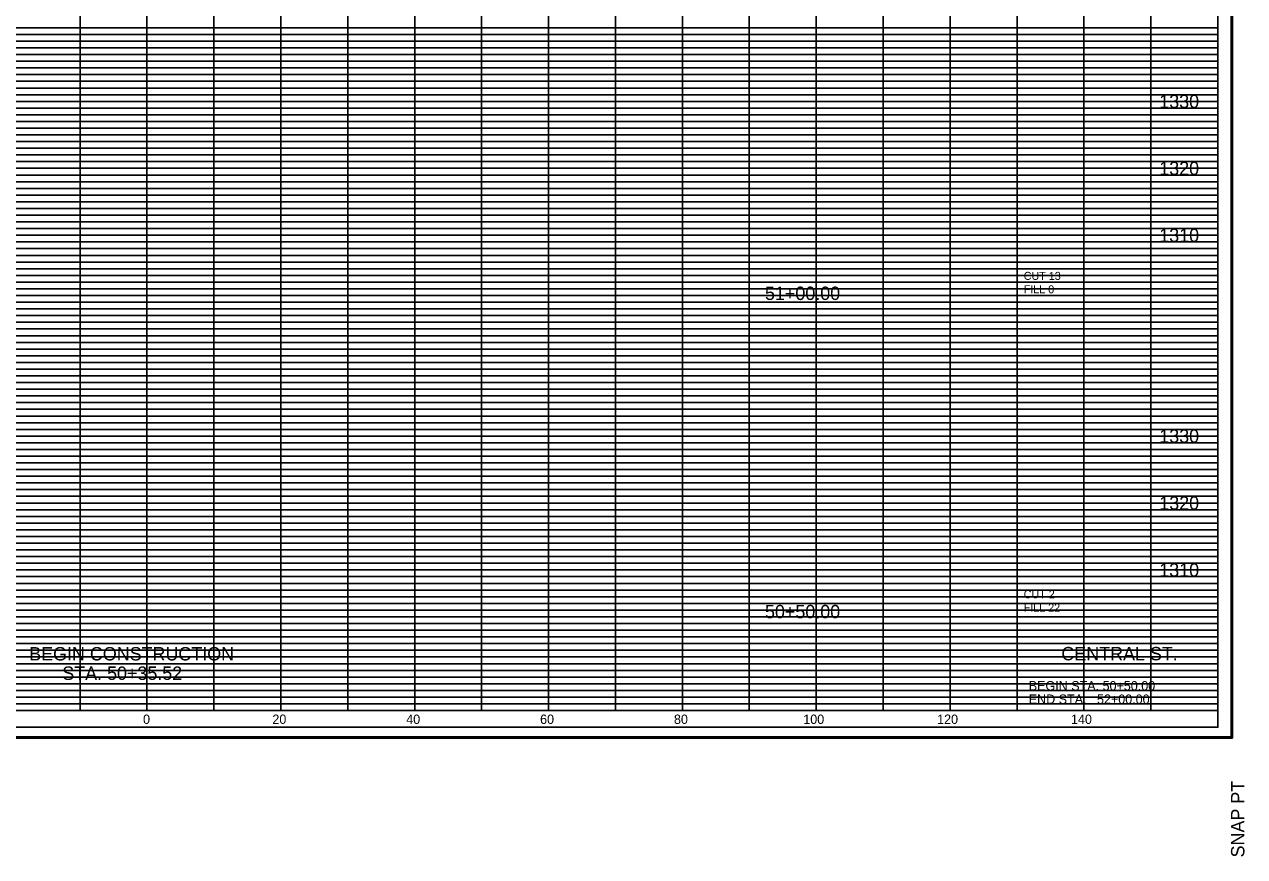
# Model space of a CAD drawing. Extents: x 980 to 1324, y 978 to 1227.
# Drawn here: x 1141.7 to 1324, y 978.2 to 1102.5 of the extents above; entities that cross this region are included whole.
import ezdxf

# ---------------------------------------------------------------- set-up
doc = ezdxf.new("R2010")
doc.units = 0
for name, color, linetype in [('DESIGN - SHEET - Corner Text', 7, 'Continuous'), ('DESIGN - SHEET - Light Grid', 7, 'Continuous'), ('DESIGN - SHEET - Linework', 7, 'Continuous'), ('DESIGN - SHEET - Plot Shape', 7, 'Continuous'), ('DESIGN - TYPICAL - Finished Grade and Subgrade', 7, 'Continuous'), ('DESIGN - TYPICAL - Text', 7, 'Continuous')]:
    doc.layers.add(name, color=color, linetype=linetype)

# ---------------------------------------------------------------- blocks, each defined once
blk = doc.blocks.new('XSTSHT')
at = {"layer": 'DESIGN - SHEET - Light Grid'}
for p, q in [((8, 10.2), (16, 10.2)), ((8, 10.1), (16, 10.1)), ((16, 10.2), (24, 10.2)), ((16, 10.1), (24, 10.1)), ((24, 10.2), (32, 10.2)), ((24, 10.1), (32, 10.1)), ((8, 9.9), (16, 9.9)), ((16, 9.9), (24, 9.9)), ((24, 9.9), (32, 9.9)), ((8, 9.8), (16, 9.8)), ((8, 9.7), (16, 9.7)), ((16, 9.8), (24, 9.8)), ((16, 9.7), (24, 9.7)), ((24, 9.8), (32, 9.8)), ((24, 9.7), (32, 9.7)), ((8, 9.6), (16, 9.6)), ((8, 9.5), (16, 9.5)), ((16, 9.6), (24, 9.6)), ((16, 9.5), (24, 9.5)), ((24, 9.6), (32, 9.6)), ((24, 9.5), (32, 9.5)), ((8, 9.4), (16, 9.4)), ((8, 9.3), (16, 9.3)), ((16, 9.4), (24, 9.4)), ((16, 9.3), (24, 9.3)), ((24, 9.4), (32, 9.4)), ((24, 9.3), (32, 9.3)), ((8, 9.2), (16, 9.2)), ((16, 9.2), (24, 9.2)), ((24, 9.2), (32, 9.2)), ((8, 9.1), (16, 9.1)), ((16, 9.1), (24, 9.1)), ((24, 9.1), (32, 9.1)), ((8, 8.9), (16, 8.9)), ((8, 8.8), (16, 8.8)), ((16, 8.9), (24, 8.9)), ((16, 8.8), (24, 8.8)), ((24, 8.9), (32, 8.9)), ((24, 8.8), (32, 8.8)), ((8, 8.7), (16, 8.7)), ((8, 8.6), (16, 8.6)), ((16, 8.7), (24, 8.7)), ((16, 8.6), (24, 8.6)), ((24, 8.7), (32, 8.7)), ((24, 8.6), (32, 8.6)), ((8, 8.5), (16, 8.5)), ((8, 8.4), (16, 8.4)), ((16, 8.5), (24, 8.5)), ((16, 8.4), (24, 8.4)), ((24, 8.5), (32, 8.5)), ((24, 8.4), (32, 8.4)), ((8, 8.3), (16, 8.3)), ((16, 8.3), (24, 8.3)), ((24, 8.3), (32, 8.3)), ((8, 8.2), (16, 8.2)), ((8, 8.1), (16, 8.1)), ((16, 8.2), (24, 8.2)), ((16, 8.1), (24, 8.1)), ((24, 8.2), (32, 8.2)), ((24, 8.1), (32, 8.1)), ((8, 7.9), (16, 7.9)), ((16, 7.9), (24, 7.9)), ((24, 7.9), (32, 7.9)), ((8, 7.8), (16, 7.8)), ((8, 7.7), (16, 7.7)), ((16, 7.8), (24, 7.8)), ((16, 7.7), (24, 7.7)), ((24, 7.8), (32, 7.8)), ((24, 7.7), (32, 7.7)), ((8, 7.6), (16, 7.6)), ((8, 7.5), (16, 7.5)), ((16, 7.6), (24, 7.6)), ((16, 7.5), (24, 7.5)), ((24, 7.6), (32, 7.6)), ((24, 7.5), (32, 7.5)), ((8, 7.4), (16, 7.4)), ((8, 7.3), (16, 7.3)), ((16, 7.4), (24, 7.4)), ((16, 7.3), (24, 7.3)), ((24, 7.4), (32, 7.4)), ((24, 7.3), (32, 7.3)), ((8, 7.2), (16, 7.2)), ((16, 7.2), (24, 7.2)), ((24, 7.2), (32, 7.2)), ((8, 7.1), (16, 7.1)), ((16, 7.1), (24, 7.1)), ((24, 7.1), (32, 7.1)), ((8, 6.9), (16, 6.9)), ((8, 6.8), (16, 6.8)), ((16, 6.9), (24, 6.9)), ((16, 6.8), (24, 6.8)), ((24, 6.9), (32, 6.9)), ((24, 6.8), (32, 6.8)), ((8, 6.7), (16, 6.7)), ((8, 6.6), (16, 6.6)), ((16, 6.7), (24, 6.7)), ((16, 6.6), (24, 6.6)), ((24, 6.7), (32, 6.7)), ((24, 6.6), (32, 6.6)), ((8, 6.5), (16, 6.5)), ((8, 6.4), (16, 6.4)), ((16, 6.5), (24, 6.5)), ((16, 6.4), (24, 6.4)), ((24, 6.5), (32, 6.5)), ((24, 6.4), (32, 6.4)), ((8, 6.3), (16, 6.3)), ((8, 6.2), (16, 6.2)), ((16, 6.3), (24, 6.3)), ((16, 6.2), (24, 6.2)), ((24, 6.3), (32, 6.3)), ((24, 6.2), (32, 6.2)), ((8, 6.1), (16, 6.1)), ((16, 6.1), (24, 6.1)), ((24, 6.1), (32, 6.1)), ((8, 5.9), (16, 5.9)), ((16, 5.9), (24, 5.9)), ((24, 5.9), (32, 5.9)), ((8, 5.8), (16, 5.8)), ((8, 5.7), (16, 5.7)), ((16, 5.8), (24, 5.8)), ((16, 5.7), (24, 5.7)), ((24, 5.8), (32, 5.8)), ((24, 5.7), (32, 5.7)), ((8, 5.6), (16, 5.6)), ((8, 5.5), (16, 5.5)), ((16, 5.6), (24, 5.6)), ((16, 5.5), (24, 5.5)), ((24, 5.6), (32, 5.6)), ((24, 5.5), (32, 5.5)), ((8, 5.4), (16, 5.4)), ((8, 5.3), (16, 5.3)), ((16, 5.4), (24, 5.4)), ((16, 5.3), (24, 5.3)), ((24, 5.4), (32, 5.4)), ((24, 5.3), (32, 5.3)), ((8, 5.2), (16, 5.2)), ((16, 5.2), (24, 5.2)), ((24, 5.2), (32, 5.2)), ((8, 5.1), (16, 5.1)), ((16, 5.1), (24, 5.1)), ((24, 5.1), (32, 5.1)), ((8, 4.9), (16, 4.9)), ((8, 4.8), (16, 4.8)), ((16, 4.9), (24, 4.9)), ((16, 4.8), (24, 4.8)), ((24, 4.9), (32, 4.9)), ((24, 4.8), (32, 4.8)), ((8, 4.7), (16, 4.7)), ((8, 4.6), (16, 4.6)), ((16, 4.7), (24, 4.7)), ((16, 4.6), (24, 4.6)), ((24, 4.7), (32, 4.7)), ((24, 4.6), (32, 4.6)), ((8, 4.5), (16, 4.5)), ((8, 4.4), (16, 4.4)), ((16, 4.5), (24, 4.5)), ((16, 4.4), (24, 4.4)), ((24, 4.5), (32, 4.5)), ((24, 4.4), (32, 4.4)), ((8, 4.3), (16, 4.3)), ((8, 4.2), (16, 4.2)), ((16, 4.3), (24, 4.3)), ((16, 4.2), (24, 4.2)), ((24, 4.3), (32, 4.3)), ((24, 4.2), (32, 4.2)), ((8, 4.1), (16, 4.1)), ((16, 4.1), (24, 4.1)), ((24, 4.1), (32, 4.1)), ((8, 3.9), (16, 3.9)), ((16, 3.9), (24, 3.9)), ((24, 3.9), (32, 3.9)), ((8, 3.8), (16, 3.8)), ((8, 3.7), (16, 3.7)), ((16, 3.8), (24, 3.8)), ((16, 3.7), (24, 3.7)), ((24, 3.8), (32, 3.8)), ((24, 3.7), (32, 3.7)), ((8, 3.6), (16, 3.6)), ((8, 3.5), (16, 3.5)), ((16, 3.6), (24, 3.6)), ((16, 3.5), (24, 3.5)), ((24, 3.6), (32, 3.6)), ((24, 3.5), (32, 3.5)), ((8, 3.4), (16, 3.4)), ((8, 3.3), (16, 3.3)), ((16, 3.4), (24, 3.4)), ((16, 3.3), (24, 3.3)), ((24, 3.4), (32, 3.4)), ((24, 3.3), (32, 3.3)), ((8, 3.2), (16, 3.2)), ((8, 3.1), (16, 3.1)), ((16, 3.2), (24, 3.2)), ((16, 3.1), (24, 3.1)), ((24, 3.2), (32, 3.2)), ((24, 3.1), (32, 3.1)), ((8, 2.9), (16, 2.9)), ((8, 2.8), (16, 2.8)), ((16, 2.9), (24, 2.9)), ((16, 2.8), (24, 2.8)), ((24, 2.9), (32, 2.9)), ((24, 2.8), (32, 2.8)), ((8, 2.7), (16, 2.7)), ((8, 2.6), (16, 2.6)), ((16, 2.7), (24, 2.7)), ((16, 2.6), (24, 2.6)), ((24, 2.7), (32, 2.7)), ((24, 2.6), (32, 2.6)), ((8, 2.5), (16, 2.5)), ((8, 2.4), (16, 2.4)), ((16, 2.5), (24, 2.5)), ((16, 2.4), (24, 2.4)), ((24, 2.5), (32, 2.5)), ((24, 2.4), (32, 2.4)), ((8, 2.3), (16, 2.3)), ((8, 2.2), (16, 2.2)), ((16, 2.3), (24, 2.3)), ((16, 2.2), (24, 2.2)), ((24, 2.3), (32, 2.3)), ((24, 2.2), (32, 2.2)), ((8, 2.1), (16, 2.1)), ((16, 2.1), (24, 2.1)), ((24, 2.1), (32, 2.1)), ((8, 1.9), (16, 1.9)), ((16, 1.9), (24, 1.9)), ((24, 1.9), (32, 1.9)), ((8, 1.8), (16, 1.8)), ((8, 1.7), (16, 1.7)), ((16, 1.8), (24, 1.8)), ((16, 1.7), (24, 1.7)), ((24, 1.8), (32, 1.8)), ((24, 1.7), (32, 1.7)), ((8, 1.6), (16, 1.6)), ((8, 1.5), (16, 1.5)), ((16, 1.6), (24, 1.6)), ((16, 1.5), (24, 1.5)), ((24, 1.6), (32, 1.6)), ((24, 1.5), (32, 1.5)), ((8, 1.4), (16, 1.4)), ((8, 1.3), (16, 1.3)), ((16, 1.4), (24, 1.4)), ((16, 1.3), (24, 1.3)), ((24, 1.4), (32, 1.4)), ((24, 1.3), (32, 1.3)), ((8, 1.2), (16, 1.2)), ((8, 1.1), (16, 1.1)), ((16, 1.2), (24, 1.2)), ((16, 1.1), (24, 1.1)), ((24, 1.2), (32, 1.2)), ((24, 1.1), (32, 1.1)), ((8, 0.9), (16, 0.9)), ((8, 0.8), (16, 0.8)), ((16, 0.9), (24, 0.9)), ((16, 0.8), (24, 0.8)), ((24, 0.9), (32, 0.9)), ((24, 0.8), (32, 0.8)), ((8, 0.7), (16, 0.7)), ((8, 0.6), (16, 0.6)), ((16, 0.7), (24, 0.7)), ((16, 0.6), (24, 0.6)), ((24, 0.7), (32, 0.7)), ((24, 0.6), (32, 0.6)), ((8, 0.5), (16, 0.5)), ((8, 0.4), (16, 0.4)), ((16, 0.5), (24, 0.5)), ((16, 0.4), (24, 0.4)), ((24, 0.5), (32, 0.5)), ((24, 0.4), (32, 0.4)), ((8, 0.3), (16, 0.3)), ((8, 0.2), (16, 0.2)), ((16, 0.3), (24, 0.3)), ((16, 0.2), (24, 0.2)), ((24, 0.3), (32, 0.3)), ((24, 0.2), (32, 0.2)), ((8, 0.1), (16, 0.1)), ((16, 0.1), (24, 0.1)), ((24, 0.1), (32, 0.1))]:
    blk.add_line(p, q, dxfattribs=at)
at = {"layer": 'DESIGN - SHEET - Linework'}
for p, q in [((32.217, 21.414), (32.217, -0.414)), ((15, 0), (15, 21)), ((16, 0), (16, 21)), ((17, 0), (17, 21)), ((18, 0), (18, 21)), ((19, 0), (19, 21)), ((20, 0), (20, 21)), ((21, 0), (21, 21)), ((22, 0), (22, 21)), ((23, 0), (23, 21)), ((24, 0), (24, 21)), ((25, 0), (25, 21)), ((26, 0), (26, 21)), ((27, 0), (27, 21)), ((28, 0), (28, 20)), ((29, 0), (29, 20)), ((30, 0), (30, 20)), ((31, 0), (31, 20)), ((0, 10), (32, 10)), ((0, 9), (32, 9)), ((0, 8), (32, 8)), ((0, 7), (32, 7)), ((0, 6), (32, 6)), ((0, 5), (32, 5)), ((0, 4), (32, 4)), ((0, 3), (32, 3)), ((0, 2), (32, 2)), ((0, 1), (32, 1)), ((-1.823, -0.414), (32.217, -0.414))]:
    blk.add_line(p, q, dxfattribs=at)
blk.add_lwpolyline([(0, 21), (0, 0), (32, 0), (32, 21), (0, 21)], dxfattribs=at)
at = {"layer": 'DESIGN - SHEET - Plot Shape'}
for points in [[(-1.803, 21.394), (32.197, 21.394), (32.197, -0.394), (-1.803, -0.394)], [(-0.85, 21), (32, 21), (32, -0.25), (-0.85, -0.25)]]:
    blk.add_lwpolyline(points, close=True, dxfattribs=at)
at = {"layer": 'DESIGN - SHEET - Corner Text'}
blk.add_text('SNAP PT  ', height=0.2, rotation=90, dxfattribs=at).set_placement((32.397, -2.194))

msp = doc.modelspace()

# ---------------------------------------------------------------- block references
at = {"layer": 'DESIGN - TYPICAL - Finished Grade and Subgrade', "xscale": 10, "yscale": 10}
msp.add_blockref('XSTSHT', (1000, 1000), dxfattribs=at)

# ---------------------------------------------------------------- texts
at = {"layer": 'DESIGN - SHEET - Corner Text'}
for s, height, p in [('1330', 2, (1311.25, 1090)), ('1320', 2, (1311.25, 1080)), ('1310', 2, (1311.25, 1070)), ('51+00.00', 2, (1252.34, 1061.33)), ('1330', 2, (1311.25, 1040)), ('1320', 2, (1311.25, 1030)), ('1310', 2, (1311.25, 1020)), ('50+50.00', 2, (1252.34, 1013.78)), ('CENTRAL ST.', 2, (1296.63, 1007.5)), ('BEGIN STA. 50+50.00', 1.4, (1291.75, 1003)), ('END STA.   52+00.00', 1.4, (1291.75, 1001)), ('0', 1.4, (1159.42, 998)), ('0', 1.4, (1159.42, 998)), ('20', 1.4, (1178.74, 998)), ('40', 1.4, (1198.74, 998)), ('60', 1.4, (1218.74, 998)), ('80', 1.4, (1238.74, 998)), ('100', 1.4, (1258.06, 998)), ('120', 1.4, (1278.06, 998)), ('140', 1.4, (1298.06, 998))]:
    msp.add_text(s, height=height, dxfattribs=at).set_placement(p)
at = {"layer": 'DESIGN - TYPICAL - Text'}
for s, height, p in [('CUT 13', 1.2, (1291, 1064.33)), ('FILL 0', 1.2, (1291, 1062.33)), ('CUT 2', 1.2, (1291, 1016.78)), ('FILL 22', 1.2, (1291, 1014.78)), ('BEGIN CONSTRUCTION', 2, (1142.41, 1007.48)), ('STA. 50+35.52', 2, (1147.35, 1004.58))]:
    msp.add_text(s, height=height, dxfattribs=at).set_placement(p)

doc.saveas('drawing.dxf')
